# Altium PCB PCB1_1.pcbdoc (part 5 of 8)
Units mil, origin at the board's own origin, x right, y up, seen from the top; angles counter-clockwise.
Board outline 3937.01 x 3346.46 mil, 6 copper layers (Top Layer, Signal-1, SIG, POWER, Signal-4, Bottom Layer), stack 60.565 mil thick; 256 components, 201 nets, 1360 pads, 815 vias.
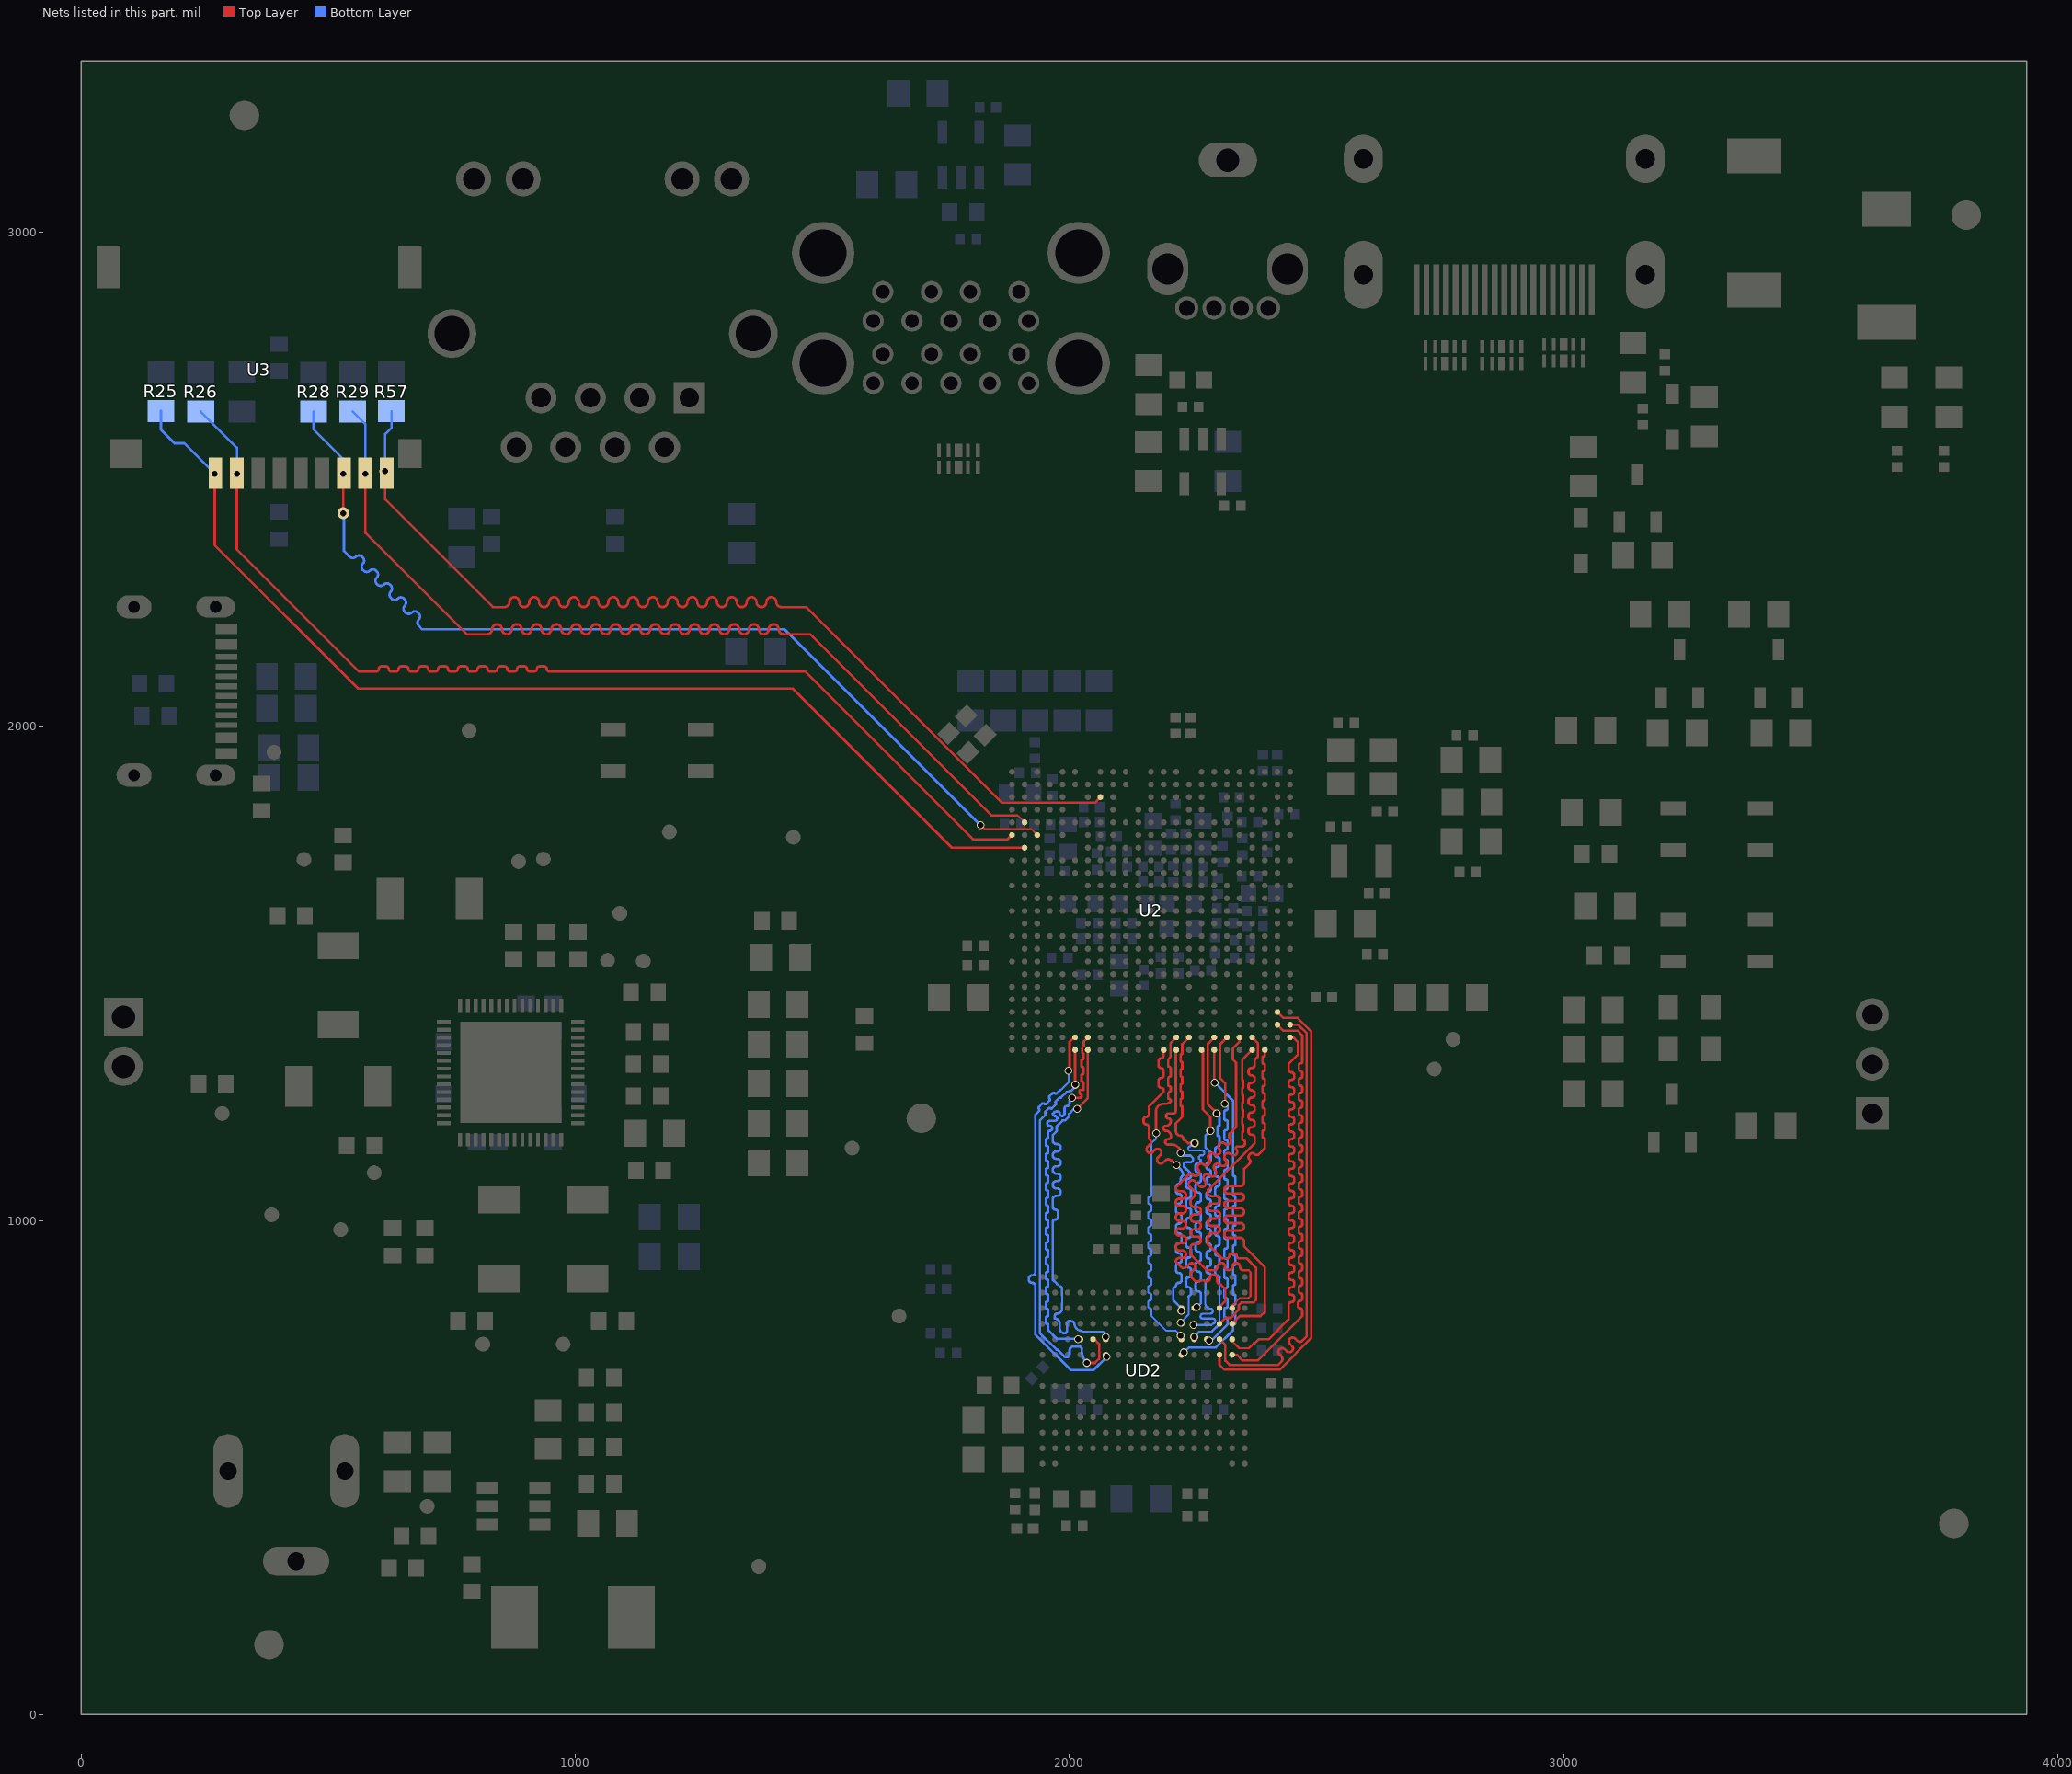
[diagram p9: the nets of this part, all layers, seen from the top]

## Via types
v1: diameter 16, hole 12, Top Layer to Bottom Layer, 426 vias
v2: diameter 24, hole 12, Top Layer to Bottom Layer, 385 vias
v3: diameter 34, hole 12, Top Layer to Bottom Layer, 2 vias
v4: diameter 30, hole 12, Top Layer to Bottom Layer, 2 vias

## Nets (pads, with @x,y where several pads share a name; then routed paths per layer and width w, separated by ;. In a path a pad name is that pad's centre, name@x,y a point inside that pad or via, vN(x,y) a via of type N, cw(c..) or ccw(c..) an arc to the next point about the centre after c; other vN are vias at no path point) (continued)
SDC0-D0: R28.1 U2.F3 U3.7 | length 2051.8
  Top Layer w4: v1(1820,1800.06) 1820.17,1800.06 1827.86,1792.36 1921.32,1792.36 1921.41,1792.28 1922.58,1792.28 1934.69,1780.17 U2.F3@1934.69,1780
  Top Layer w5: v2(530,2431.46) v2(530,2511.46) U3.7@531.26,2512.8
  Bottom Layer w5: R28.1@470.16,2637.13 470.16,2601.29 530,2541.46 v2(530,2511.46) ; v2(530,2431.46) 531.46,2429.99 531.46,2354.99 543.09,2343.37 ccw(c549.34,2349.62) 555.59,2343.37 cw(c561.84,2337.12) 568.09,2343.37 569.73,2341.73 cw(c563.48,2335.48) 569.73,2329.23 ccw(c575.98,2322.98) 569.73,2316.73 571.37,2315.08 ccw(c577.62,2321.33) 583.87,2315.08 cw(c590.12,2308.83) 596.37,2315.08 598.01,2313.44 cw(c591.76,2307.19) 598.01,2300.94 ccw(c604.26,2294.69) 598.01,2288.44 599.66,2286.8 ccw(c605.91,2293.05) 612.16,2286.8 cw(c618.41,2280.55) 624.66,2286.8 626.3,2285.16 cw(c620.05,2278.91) 626.3,2272.66 ccw(c632.55,2266.41) 626.3,2260.16 627.94,2258.52 ccw(c634.19,2264.77) 640.44,2258.52 cw(c646.69,2252.27) 652.94,2258.52 654.58,2256.87 cw(c648.33,2250.62) 654.58,2244.37 ccw(c660.83,2238.12) 654.58,2231.87 656.23,2230.23 ccw(c662.48,2236.48) 668.73,2230.23 cw(c674.98,2223.98) 681.23,2230.23 682.87,2228.59 cw(c676.62,2222.34) 682.87,2216.09 ccw(c689.12,2209.84) 682.87,2203.59 690,2196.46 1423.6,2196.46 v1(1820,1800.06)
SDC0-D1: R29.1 U2.E2 U3.8 | length 2175.2
  Top Layer w4: 1841.96,1819.5 1895.19,1819.5 U2.E2@1909.09,1805.59
  Top Layer w5: v2(575,2511.46) 575,2391.46 780,2186.46 821.28,2186.46 ccw(c821.28,2196.46) 831.28,2196.46 cw(c841.28,2196.46) 851.28,2196.46 ccw(c861.28,2196.46) 871.28,2196.46 cw(c881.28,2196.46) 891.28,2196.46 ccw(c901.28,2196.46) 911.28,2196.46 cw(c921.28,2196.46) 931.28,2196.46 ccw(c941.28,2196.46) 951.28,2196.46 cw(c961.28,2196.46) 971.28,2196.46 ccw(c981.28,2196.46) 991.28,2196.46 cw(c1001.28,2196.46) 1011.28,2196.46 ccw(c1021.28,2196.46) 1031.28,2196.46 cw(c1041.28,2196.46) 1051.28,2196.46 ccw(c1061.28,2196.46) 1071.28,2196.46 cw(c1081.28,2196.46) 1091.28,2196.46 ccw(c1101.28,2196.46) 1111.28,2196.46 cw(c1121.28,2196.46) 1131.28,2196.46 ccw(c1141.28,2196.46) 1151.28,2196.46 cw(c1161.28,2196.46) 1171.28,2196.46 ccw(c1181.28,2196.46) 1191.28,2196.46 cw(c1201.28,2196.46) 1211.28,2196.46 ccw(c1221.28,2196.46) 1231.28,2196.46 cw(c1241.28,2196.46) 1251.28,2196.46 ccw(c1261.28,2196.46) 1271.28,2196.46 cw(c1281.28,2196.46) 1291.28,2196.46 ccw(c1301.28,2196.46) 1311.28,2196.46 cw(c1321.28,2196.46) 1331.28,2196.46 ccw(c1341.28,2196.46) 1351.28,2196.46 cw(c1361.28,2196.46) 1371.28,2196.46 ccw(c1381.28,2196.46) 1391.28,2196.46 cw(c1401.28,2196.46) 1411.28,2196.46 ccw(c1421.28,2196.46) 1421.28,2186.46 1475,2186.46 1841.68,1819.78
  Bottom Layer w5: R29.1@549.18,2637.16 575,2611.33 v2(575,2511.46)
SDC0-D2: R25.1 U2.G2 U3.1 | length 2221.5
  Top Layer w5: v2(270,2511.46) 270,2366.46 560,2076.46 1440,2076.46 1762.05,1754.41 U2.G2@1909.09,1754.41
  Bottom Layer w5: R25.1@161.03,2638.49 161.03,2600.43 188.54,2572.92 208.54,2572.92 v2(270,2511.46)
SDC0-D3: R26.1 U2.F1 U3.2 | length 2228.8
  Top Layer w5: U3.2@314.72,2512.8 314.72,2358.32 561.58,2111.46 597.02,2111.46 ccw(c597.02,2116.46) 602.02,2116.46 cw(c607.02,2116.46) 607.02,2121.46 617.02,2121.46 cw(c617.02,2116.46) 622.02,2116.46 ccw(c627.02,2116.46) 627.02,2111.46 637.02,2111.46 ccw(c637.02,2116.46) 642.02,2116.46 cw(c647.02,2116.46) 647.02,2121.46 657.02,2121.46 cw(c657.02,2116.46) 662.02,2116.46 ccw(c667.02,2116.46) 667.02,2111.46 677.02,2111.46 ccw(c677.02,2116.46) 682.02,2116.46 cw(c687.02,2116.46) 687.02,2121.46 697.02,2121.46 cw(c697.02,2116.46) 702.02,2116.46 ccw(c707.02,2116.46) 707.02,2111.46 717.02,2111.46 ccw(c717.02,2116.46) 722.02,2116.46 cw(c727.02,2116.46) 727.02,2121.46 737.02,2121.46 cw(c737.02,2116.46) 742.02,2116.46 ccw(c747.02,2116.46) 747.02,2111.46 757.02,2111.46 ccw(c757.02,2116.46) 762.02,2116.46 cw(c767.02,2116.46) 767.02,2121.46 777.02,2121.46 cw(c777.02,2116.46) 782.02,2116.46 ccw(c787.02,2116.46) 787.02,2111.46 797.02,2111.46 ccw(c797.02,2116.46) 802.02,2116.46 cw(c807.02,2116.46) 807.02,2121.46 817.02,2121.46 cw(c817.02,2116.46) 822.02,2116.46 ccw(c827.02,2116.46) 827.02,2111.46 837.02,2111.46 ccw(c837.02,2116.46) 842.02,2116.46 cw(c847.02,2116.46) 847.02,2121.46 857.02,2121.46 cw(c857.02,2116.46) 862.02,2116.46 ccw(c867.02,2116.46) 867.02,2111.46 877.02,2111.46 ccw(c877.02,2116.46) 882.02,2116.46 cw(c887.02,2116.46) 887.02,2121.46 897.02,2121.46 cw(c897.02,2116.46) 902.02,2116.46 ccw(c907.02,2116.46) 907.02,2111.46 917.02,2111.46 ccw(c917.02,2116.46) 922.02,2116.46 cw(c927.02,2116.46) 927.02,2121.46 937.02,2121.46 cw(c937.02,2116.46) 942.02,2116.46 ccw(c947.02,2116.46) 947.02,2111.46 1464.81,2111.46 1804.81,1771.46 1874.96,1771.46 U2.F1@1883.5,1780
  Bottom Layer w5: R26.1@241.48,2637.19 315,2563.67 v2(315,2511.46)
SDC0-DET: R57.1 U2.C8 U3.CD | length 2210.1
  Top Layer w5: v2(615,2516.46) 615,2459.18 832.73,2241.46 856.53,2241.46 ccw(c856.53,2251.46) 866.53,2251.46 cw(c876.53,2251.46) 886.53,2251.46 ccw(c896.53,2251.46) 906.53,2251.46 cw(c916.53,2251.46) 926.53,2251.46 ccw(c936.53,2251.46) 946.53,2251.46 cw(c956.53,2251.46) 966.53,2251.46 ccw(c976.53,2251.46) 986.53,2251.46 cw(c996.53,2251.46) 1006.53,2251.46 ccw(c1016.53,2251.46) 1026.53,2251.46 cw(c1036.53,2251.46) 1046.53,2251.46 ccw(c1056.53,2251.46) 1066.53,2251.46 cw(c1076.53,2251.46) 1086.53,2251.46 ccw(c1096.53,2251.46) 1106.53,2251.46 cw(c1116.53,2251.46) 1126.53,2251.46 ccw(c1136.53,2251.46) 1146.53,2251.46 cw(c1156.53,2251.46) 1166.53,2251.46 ccw(c1176.53,2251.46) 1186.53,2251.46 cw(c1196.53,2251.46) 1206.53,2251.46 ccw(c1216.53,2251.46) 1226.53,2251.46 cw(c1236.53,2251.46) 1246.53,2251.46 ccw(c1256.53,2251.46) 1266.53,2251.46 cw(c1276.53,2251.46) 1286.53,2251.46 ccw(c1296.53,2251.46) 1306.53,2251.46 cw(c1316.53,2251.46) 1326.53,2251.46 ccw(c1336.53,2251.46) 1346.53,2251.46 cw(c1356.53,2251.46) 1366.53,2251.46 ccw(c1376.53,2251.46) 1386.53,2251.46 cw(c1396.53,2251.46) 1406.53,2251.46 ccw(c1416.53,2251.46) 1416.53,2241.46 1467.17,2241.46 1863.26,1845.37 2051.23,1845.37 U2.C8@2062.64,1856.77
  Bottom Layer w5: v2(615,2516.46) 615,2591.46 627.65,2604.11 R57.1@627.65,2637.78
SDQ0: U2.AB18 UD2.P9 | length 731
  Top Layer w5: v1(2314.55,1236.01) 2315,1236.46 2315,1277.67 2305,1287.67 2305,1357.01 U2.AB18@2318.54,1370.55
  Bottom Layer w5: v1(2282.95,756.95) 2287.49,756.98 2320,789.49 2320,799.4 ccw(c2316.53,799.4) 2316.53,802.88 cw(c2316.53,806.35) 2313.05,806.35 2313.05,819.4 cw(c2316.53,819.4) 2316.53,822.88 ccw(c2316.53,826.35) 2320,826.35 2320,839.4 ccw(c2316.53,839.4) 2316.53,842.88 cw(c2316.53,846.35) 2313.05,846.35 2313.05,859.4 cw(c2316.53,859.4) 2316.53,862.88 ccw(c2316.53,866.35) 2320,866.35 2320,879.4 ccw(c2316.53,879.4) 2316.53,882.88 cw(c2316.53,886.35) 2313.05,886.35 2313.05,899.4 cw(c2316.53,899.4) 2316.53,902.88 ccw(c2316.53,906.35) 2320,906.35 2320,919.4 ccw(c2316.53,919.4) 2316.53,922.88 cw(c2316.53,926.35) 2313.05,926.35 2313.05,939.4 cw(c2316.53,939.4) 2316.53,942.88 ccw(c2316.53,946.35) 2320,946.35 2320,959.4 ccw(c2316.53,959.4) 2316.53,962.88 cw(c2316.53,966.35) 2313.05,966.35 2313.05,979.4 cw(c2316.53,979.4) 2316.53,982.88 ccw(c2316.53,986.35) 2320,986.35 2320,999.4 ccw(c2316.53,999.4) 2316.53,1002.88 cw(c2316.53,1006.35) 2313.05,1006.35 2313.05,1019.4 cw(c2316.53,1019.4) 2316.53,1022.88 ccw(c2316.53,1026.35) 2320,1026.35 2320,1039.4 ccw(c2316.53,1039.4) 2316.53,1042.88 cw(c2316.53,1046.35) 2313.05,1046.35 2313.05,1059.4 cw(c2316.53,1059.4) 2316.53,1062.88 ccw(c2316.53,1066.35) 2320,1066.35 2320,1079.4 ccw(c2316.53,1079.4) 2316.53,1082.88 cw(c2316.53,1086.35) 2313.05,1086.35 2313.05,1099.4 cw(c2316.53,1099.4) 2316.53,1102.88 ccw(c2316.53,1106.35) 2320,1106.35 2320,1119.4 ccw(c2316.53,1119.4) 2316.53,1122.88 cw(c2316.53,1126.35) 2313.05,1126.35 2313.05,1139.4 cw(c2316.53,1139.4) 2316.53,1142.88 ccw(c2316.53,1146.35) 2320,1146.35 2320,1159.4 ccw(c2316.53,1159.4) 2316.53,1162.88 cw(c2316.53,1166.35) 2313.05,1166.35 2313.05,1179.4 cw(c2316.53,1179.4) 2316.53,1182.88 ccw(c2316.53,1186.35) 2320,1186.35 2320,1199.4 ccw(c2316.53,1199.4) 2316.53,1202.88 cw(c2316.53,1206.35) 2313.05,1206.35 2313.05,1219.4 cw(c2316.53,1219.4) 2316.53,1222.88 ccw(c2316.53,1226.35) 2320,1226.35 2320,1230.56 v1(2314.55,1236.01)
SDQ1: U2.AC17 UD2.M8 | length 742
  Top Layer w5: U2.AC17@2292.95,1344.96 2292.95,1279.94 v1(2294,1278.9)
  Bottom Layer w5: v1(2231.77,732.95) 2241.77,742.95 2296.5,742.95 2331,777.46 2331,787.33 cw(c2333.25,787.33) 2333.25,789.58 ccw(c2333.25,791.83) 2335.5,791.83 2335.5,807.33 ccw(c2333.25,807.33) 2333.25,809.58 cw(c2333.25,811.83) 2331,811.83 2331,827.33 cw(c2333.25,827.33) 2333.25,829.58 ccw(c2333.25,831.83) 2335.5,831.83 2335.5,847.33 ccw(c2333.25,847.33) 2333.25,849.58 cw(c2333.25,851.83) 2331,851.83 2331,867.33 cw(c2333.25,867.33) 2333.25,869.58 ccw(c2333.25,871.83) 2335.5,871.83 2335.5,887.33 ccw(c2333.25,887.33) 2333.25,889.58 cw(c2333.25,891.83) 2331,891.83 2331,907.33 cw(c2333.25,907.33) 2333.25,909.58 ccw(c2333.25,911.83) 2335.5,911.83 2335.5,927.33 ccw(c2333.25,927.33) 2333.25,929.58 cw(c2333.25,931.83) 2331,931.83 2331,947.33 cw(c2333.25,947.33) 2333.25,949.58 ccw(c2333.25,951.83) 2335.5,951.83 2335.5,967.33 ccw(c2333.25,967.33) 2333.25,969.58 cw(c2333.25,971.83) 2331,971.83 2331,987.33 cw(c2333.25,987.33) 2333.25,989.58 ccw(c2333.25,991.83) 2335.5,991.83 2335.5,1007.33 ccw(c2333.25,1007.33) 2333.25,1009.58 cw(c2333.25,1011.83) 2331,1011.83 2331,1027.33 cw(c2333.25,1027.33) 2333.25,1029.58 ccw(c2333.25,1031.83) 2335.5,1031.83 2335.5,1047.33 ccw(c2333.25,1047.33) 2333.25,1049.58 cw(c2333.25,1051.83) 2331,1051.83 2331,1067.33 cw(c2333.25,1067.33) 2333.25,1069.58 ccw(c2333.25,1071.83) 2335.5,1071.83 2335.5,1087.33 ccw(c2333.25,1087.33) 2333.25,1089.58 cw(c2333.25,1091.83) 2331,1091.83 2331,1241.9 v1(2294,1278.9)
SDQ2: U2.AB17 UD2.N9 | length 730.7
  Top Layer w5: U2.AB17@2292.95,1370.55 2280,1357.6 2280,1235.01 v1@2298.55,1216.46
  Bottom Layer w3.5: 2304.05,790.51 2304.05,883.83
  Bottom Layer w5: v1(2252.36,764.45) 2262.36,774.45 2287.99,774.45 2304.05,790.51 ; v1@2298.55,1216.46 2303.55,1211.46 2303.55,1192.88 cw(c2301.55,1192.88) 2301.55,1190.88 ccw(c2301.55,1188.88) 2299.55,1188.88 2299.55,1172.88 ccw(c2301.55,1172.88) 2301.55,1170.88 cw(c2301.55,1168.88) 2303.55,1168.88 2303.55,1152.88 cw(c2299.28,1152.88) 2299.28,1148.61 ccw(c2299.28,1144.33) 2295,1144.33 2295,1132.88 ccw(c2299.28,1132.88) 2299.28,1128.61 cw(c2299.28,1124.33) 2303.55,1124.33 2303.55,1112.88 cw(c2299.28,1112.88) 2299.28,1108.61 ccw(c2299.28,1104.33) 2295,1104.33 2295,1092.88 ccw(c2299.28,1092.88) 2299.28,1088.61 cw(c2299.28,1084.33) 2303.55,1084.33 2303.55,1072.88 cw(c2299.28,1072.88) 2299.28,1068.61 ccw(c2299.28,1064.33) 2295,1064.33 2295,1052.88 ccw(c2299.28,1052.88) 2299.28,1048.61 cw(c2299.28,1044.33) 2303.55,1044.33 2303.55,1032.88 cw(c2299.28,1032.88) 2299.28,1028.61 ccw(c2299.28,1024.33) 2295,1024.33 2295,1012.88 ccw(c2299.28,1012.88) 2299.28,1008.61 cw(c2299.28,1004.33) 2303.55,1004.33 2303.55,992.88 cw(c2299.28,992.88) 2299.28,988.61 ccw(c2299.28,984.33) 2295,984.33 2295,972.88 ccw(c2299.28,972.88) 2299.28,968.61 cw(c2299.28,964.33) 2303.55,964.33 2303.55,952.88 cw(c2299.28,952.88) 2299.28,948.61 ccw(c2299.28,944.33) 2295,944.33 2295,932.88 ccw(c2299.28,932.88) 2299.28,928.61 cw(c2299.28,924.33) 2303.55,924.33 2303.55,912.88 cw(c2299.28,912.88) 2299.28,908.61 ccw(c2299.28,904.33) 2295,904.33 2295,892.88 ccw(c2299.28,892.88) 2299.28,888.61 cw(c2299.28,884.33) 2303.55,884.33 2304.05,883.83
  other v1: 2298,1216.46
SDQ3: U2.AC16 UD2.N10 | length 752.7
  Top Layer w5: U2.AC16@2267.36,1344.96 2270,1342.32 2270,1224.66 2285,1209.66 v1(2285,1181.51)
  Bottom Layer w4: v1(2250.72,788.25) 2287.31,788.25 2290,790.94 ccw(c2290,795.94) 2295,795.94 ccw(c2289.49,795.94) 2289.49,801.46 2269,801.46 cw(c2269,805.46) 2265,805.46 cw(c2271,805.46) 2271,811.46 2285,811.46 ccw(c2285,816.46) 2290,816.46 ccw(c2285,816.46) 2285,821.46 cw(c2285,831.46) 2275,831.46 2274.63,831.82 2274.63,861.09 2275,861.46
  Bottom Layer w5: 2275,861.46 2275,876.5 2286,887.5 2286,888.68 ccw(c2281.63,888.68) 2281.63,893.05 cw(c2281.63,897.42) 2277.26,897.42 2277.26,903.68 cw(c2281.63,903.68) 2281.63,908.05 ccw(c2281.63,912.42) 2286,912.42 2286,918.68 ccw(c2281.63,918.68) 2281.63,923.05 cw(c2281.63,927.42) 2277.26,927.42 2277.26,933.68 cw(c2281.63,933.68) 2281.63,938.05 ccw(c2281.63,942.42) 2286,942.42 2286,948.68 ccw(c2281.63,948.68) 2281.63,953.05 cw(c2281.63,957.42) 2277.26,957.42 2277.26,963.68 cw(c2281.63,963.68) 2281.63,968.05 ccw(c2281.63,972.42) 2286,972.42 2286,978.68 ccw(c2281.63,978.68) 2281.63,983.05 cw(c2281.63,987.42) 2277.26,987.42 2277.26,993.68 cw(c2281.63,993.68) 2281.63,998.05 ccw(c2281.63,1002.42) 2286,1002.42 2286,1008.68 ccw(c2281.63,1008.68) 2281.63,1013.05 cw(c2281.63,1017.42) 2277.26,1017.42 2277.26,1023.68 cw(c2281.63,1023.68) 2281.63,1028.05 ccw(c2281.63,1032.42) 2286,1032.42 2286,1038.68 ccw(c2281.63,1038.68) 2281.63,1043.05 cw(c2281.63,1047.42) 2277.26,1047.42 2277.26,1053.68 cw(c2281.63,1053.68) 2281.63,1058.05 ccw(c2281.63,1062.42) 2286,1062.42 2286,1068.68 ccw(c2281.63,1068.68) 2281.63,1073.05 cw(c2281.63,1077.42) 2277.26,1077.42 2277.26,1083.68 cw(c2281.63,1083.68) 2281.63,1088.05 ccw(c2281.63,1092.42) 2286,1092.42 2286,1098.68 ccw(c2281.63,1098.68) 2281.63,1103.05 cw(c2281.63,1107.42) 2277.26,1107.42 2277.26,1113.68 cw(c2281.63,1113.68) 2281.63,1118.05 ccw(c2281.63,1122.42) 2286,1122.42 2286,1137.48 2275,1148.48 2275,1171.51 v1(2285,1181.51)
SDQ4: U2.AB15 UD2.N11 | length 737.8
  Top Layer w5: U2.AB15@2241.77,1370.55 2228.18,1356.96 2228.18,1337.65 cw(c2226.59,1337.65) 2226.59,1336.05 ccw(c2226.59,1334.46) 2225,1334.46 2225,1322.65 ccw(c2226.59,1322.65) 2226.59,1321.05 cw(c2226.59,1319.46) 2228.18,1319.46 2228.18,1307.65 cw(c2226.59,1307.65) 2226.59,1306.05 ccw(c2226.59,1304.46) 2225,1304.46 2225,1292.65 ccw(c2226.59,1292.65) 2226.59,1291.05 cw(c2226.59,1289.46) 2228.18,1289.46 2228.18,1277.65 cw(c2226.59,1277.65) 2226.59,1276.05 ccw(c2226.59,1274.46) 2225,1274.46 2225,1262.65 ccw(c2226.59,1262.65) 2226.59,1261.05 cw(c2226.59,1259.46) 2228.18,1259.46 2228.18,1247.65 cw(c2226.59,1247.65) 2226.59,1246.05 ccw(c2226.59,1244.46) 2225,1244.46 2225,1232.65 ccw(c2226.59,1232.65) 2226.59,1231.05 cw(c2226.59,1229.46) 2228.18,1229.46 2228.18,1209.64 2215,1196.46 2215,1181.46 ccw(c2225,1181.46) 2225,1171.46 cw(c2225,1166.46) 2230,1166.46 ccw(c2235,1166.46) 2235,1161.46 2240,1156.46 v1(2253.33,1156.46)
  Bottom Layer w4: 2244.13,1149.96 2242.54,1149.96 2240.05,1147.47 2240.05,1143.95 2242.54,1141.46 2270,1141.46 2272.83,1138.63 2272.83,1134.78 2269.85,1131.8 2265,1131.8 2262.17,1128.97 2262.17,1124.97 2265.23,1121.92 2266.13,1121.92
  Bottom Layer w5: 2244.13,1149.96 2245.63,1151.46 2251.25,1151.46 2253.33,1153.53 v1(2253.33,1156.46) ; v1(2257.8,824.29) 2266.13,832.62 2266.13,851.05 ccw(c2260.7,851.05) 2260.7,856.49 cw(c2260.7,861.92) 2255.27,861.92 2255.27,871.05 cw(c2260.7,871.05) 2260.7,876.49 ccw(c2260.7,881.92) 2266.13,881.92 2266.13,891.05 ccw(c2260.7,891.05) 2260.7,896.49 cw(c2260.7,901.92) 2255.27,901.92 2255.27,911.05 cw(c2260.7,911.05) 2260.7,916.49 ccw(c2260.7,921.92) 2266.13,921.92 2266.13,931.05 ccw(c2260.7,931.05) 2260.7,936.49 cw(c2260.7,941.92) 2255.27,941.92 2255.27,951.05 cw(c2260.7,951.05) 2260.7,956.49 ccw(c2260.7,961.92) 2266.13,961.92 2266.13,971.05 ccw(c2260.7,971.05) 2260.7,976.49 cw(c2260.7,981.92) 2255.27,981.92 2255.27,991.05 cw(c2260.7,991.05) 2260.7,996.49 ccw(c2260.7,1001.92) 2266.13,1001.92 2266.13,1011.05 ccw(c2260.7,1011.05) 2260.7,1016.49 cw(c2260.7,1021.92) 2255.27,1021.92 2255.27,1031.05 cw(c2260.7,1031.05) 2260.7,1036.49 ccw(c2260.7,1041.92) 2266.13,1041.92 2266.13,1051.05 ccw(c2260.7,1051.05) 2260.7,1056.49 cw(c2260.7,1061.92) 2255.27,1061.92 2255.27,1071.05 cw(c2260.7,1071.05) 2260.7,1076.49 ccw(c2260.7,1081.92) 2266.13,1081.92 2266.13,1091.05 ccw(c2260.7,1091.05) 2260.7,1096.49 cw(c2260.7,1101.92) 2255.27,1101.92 2255.27,1111.05 cw(c2260.7,1111.05) 2260.7,1116.49 ccw(c2260.7,1121.92) 2266.13,1121.92
SDQ5: U2.AB14 UD2.M9 | length 742.5
  Top Layer w5: v1(2175.32,1176.77) cw(c2176.08,1177.53) 2175,1177.53 2175,1220.25 cw(c2191.21,1220.25) 2179.75,1231.71 cw(c2190,1221.46) 2190,1235.96 2193.43,1235.96 ccw(c2193.43,1252.67) 2205.25,1240.85 ccw(c2204.65,1241.46) 2205.5,1241.46 ccw(c2200.5,1241.46) 2200.5,1246.46 cw(c2200.5,1246.96) 2200,1246.96 2200,1256.46 cw(c2205,1256.46) 2205,1261.46 2205,1268.96 ccw(c2202.5,1268.96) 2202.5,1271.46 cw(c2202.5,1273.96) 2200,1273.96 2200,1286.46 cw(c2205,1286.46) 2205,1291.46 2205,1306.46 ccw(c2200,1306.46) 2200,1311.46 2200,1326.46 2204.28,1330.73 2204.28,1358.65 U2.AB14@2216.18,1370.55
  Bottom Layer w4: v1(2175.32,1176.77) 2175.32,1165.86 2165.5,1156.05 2165.5,1050.84 cw(c2162.38,1050.84) 2162.38,1047.72 ccw(c2162.38,1044.6) 2159.26,1044.6 2159.26,1035.84 ccw(c2162.38,1035.84) 2162.38,1032.72 cw(c2162.38,1029.6) 2165.5,1029.6 2165.5,1020.84 cw(c2162.38,1020.84) 2162.38,1017.72 ccw(c2162.38,1014.6) 2159.26,1014.6 2159.26,1005.84 ccw(c2162.38,1005.84) 2162.38,1002.72 cw(c2162.38,999.6) 2165.5,999.6 2165.5,990.84 cw(c2162.38,990.84) 2162.38,987.72 ccw(c2162.38,984.6) 2159.26,984.6 2159.26,975.84 ccw(c2162.38,975.84) 2162.38,972.72 cw(c2162.38,969.6) 2165.5,969.6 2165.5,960.84 cw(c2162.38,960.84) 2162.38,957.72 ccw(c2162.38,954.6) 2159.26,954.6 2159.26,945.84 ccw(c2162.38,945.84) 2162.38,942.72 cw(c2162.38,939.6) 2165.5,939.6 2165.5,930.84 cw(c2162.38,930.84) 2162.38,927.72 ccw(c2162.38,924.6) 2159.26,924.6 2159.26,915.84 ccw(c2162.38,915.84) 2162.38,912.72 cw(c2162.38,909.6) 2165.5,909.6 2165.5,900.84 cw(c2162.38,900.84) 2162.38,897.72 ccw(c2162.38,894.6) 2159.26,894.6 2159.26,885.84 ccw(c2162.38,885.84) 2162.38,882.72 cw(c2162.38,879.6) 2165.5,879.6 2165.5,870.84 cw(c2162.38,870.84) 2162.38,867.72 ccw(c2162.38,864.6) 2159.26,864.6 2159.26,855.84 ccw(c2162.38,855.84) 2162.38,852.72 cw(c2162.38,849.6) 2165.5,849.6 2165.5,840.84 cw(c2162.38,840.84) 2162.38,837.72 ccw(c2162.38,834.6) 2159.26,834.6 2159.26,825.84 ccw(c2162.38,825.84) 2162.38,822.72 cw(c2162.38,819.6) 2165.5,819.6 2165.5,806.83 2195.38,776.94 2214.51,776.94 v1(2225,766.46)
SDQ6: U2.AC14 UD2.M10 | length 736.8
  Top Layer w5: U2.AC14@2216.18,1344.96 ccw(c2216.18,1343.78) 2215,1343.78 2215,1221.46 cw(c2210,1221.46) 2210,1216.46 2200,1216.46 ccw(c2200,1211.46) 2195,1211.46 ccw(c2200,1211.46) 2200,1206.46 cw(c2200,1201.46) 2205,1201.46 cw(c2195,1201.46) 2195,1191.46 ccw(c2195,1186.46) 2190,1186.46 ccw(c2195,1186.46) 2195,1181.46 cw(c2195,1170.92) 2205.54,1170.92 2205.54,1170.4 cw(c2199.71,1170.4) 2199.71,1164.58 ccw(c2199.71,1158.58) 2193.71,1158.58 ccw(c2198.71,1158.58) 2198.71,1153.58 2206.64,1153.58 cw(c2206.64,1133.51) v1@2226.71,1133.51
  Bottom Layer w4: v1(2224.87,793.21) 2241.27,809.61 2241.27,844.78 2240.77,845.28
  Bottom Layer w5: v1(2225,1136.46) 2230,1131.46 2245,1131.46 2250,1126.46 2250,1121.46 2246.46,1117.92 2235,1117.92 2231.46,1114.39 2231.46,1109.39 2245.77,1095.08 2245.77,1089.56 cw(c2241.02,1089.56) 2241.02,1084.81 ccw(c2241.02,1080.06) 2236.27,1080.06 2236.27,1069.56 ccw(c2241.02,1069.56) 2241.02,1064.81 cw(c2241.02,1060.06) 2245.77,1060.06 2245.77,1049.56 cw(c2241.02,1049.56) 2241.02,1044.81 ccw(c2241.02,1040.06) 2236.27,1040.06 2236.27,1029.56 ccw(c2241.02,1029.56) 2241.02,1024.81 cw(c2241.02,1020.06) 2245.77,1020.06 2245.77,1009.56 cw(c2241.02,1009.56) 2241.02,1004.81 ccw(c2241.02,1000.06) 2236.27,1000.06 2236.27,989.56 ccw(c2241.02,989.56) 2241.02,984.81 cw(c2241.02,980.06) 2245.77,980.06 2245.77,969.56 cw(c2241.02,969.56) 2241.02,964.81 ccw(c2241.02,960.06) 2236.27,960.06 2236.27,949.56 ccw(c2241.02,949.56) 2241.02,944.81 cw(c2241.02,940.06) 2245.77,940.06 2245.77,929.56 cw(c2241.02,929.56) 2241.02,924.81 ccw(c2241.02,920.06) 2236.27,920.06 2236.27,909.56 ccw(c2241.02,909.56) 2241.02,904.81 cw(c2241.02,900.06) 2245.77,900.06 2245.77,889.56 cw(c2241.02,889.56) 2241.02,884.81 ccw(c2241.02,880.06) 2236.27,880.06 2236.27,869.56 ccw(c2241.02,869.56) 2241.02,864.81 cw(c2241.02,860.06) 2245.77,860.06 2245.77,850.28 2240.77,845.28
SDQ7: U2.AC13 UD2.M11 | length 742.1
  Top Layer w5: U2.AC13@2190.59,1344.96 2190.59,1333.68 cw(c2185.3,1333.68) 2185.3,1328.38 ccw(c2185.3,1323.09) 2180,1323.09 2180,1313.68 ccw(c2185.3,1313.68) 2185.3,1308.38 cw(c2185.3,1303.09) 2190.59,1303.09 2190.59,1293.68 cw(c2185.3,1293.68) 2185.3,1288.38 ccw(c2185.3,1283.09) 2180,1283.09 2180,1273.68 ccw(c2185.3,1273.68) 2185.3,1268.38 cw(c2185.3,1263.09) 2190.59,1263.09 2190.59,1260.48 2160.5,1230.39 2160.5,1214.72 cw(c2155.25,1214.72) 2155.25,1209.47 ccw(c2155.25,1204.22) 2150,1204.22 2150,1199.72 ccw(c2155.25,1199.72) 2155.25,1194.47 cw(c2155.25,1189.22) 2160.5,1189.22 2160.5,1166.08 2162.52,1164.06 cw(c2157.21,1158.76) 2162.52,1153.46 2158.3,1149.24 ccw(c2163.6,1143.93) 2168.9,1138.63 2173.12,1142.85 cw(c2178.43,1137.55) 2183.73,1132.24 2179.51,1128.02 ccw(c2184.81,1122.72) 2190.12,1117.42 2194.34,1121.64 cw(c2199.64,1116.33) 2204.94,1121.64 2206.94,1121.64 v1(2216.17,1112.41)
  Bottom Layer w5: v1(2216.17,1112.41) 2223.64,1104.94 ccw(c2231.46,1109.39) 2225.1,1103.02 2225.29,1102.84 cw(c2213.91,1091.46) 2230,1091.46 2228.2,1089.66 ccw(c2235.93,1081.93) 2225,1081.93 cw(c2214.07,1081.93) 2221.8,1074.2 2221.23,1073.63 ccw(c2221.23,1068.08) 2215.68,1068.08 2215.68,1059.17 ccw(c2221.23,1059.17) 2221.23,1053.63 cw(c2221.23,1048.08) 2226.77,1048.08 2226.77,1039.17 cw(c2221.23,1039.17) 2221.23,1033.63 ccw(c2221.23,1028.08) 2215.68,1028.08 2215.68,1019.17 ccw(c2221.23,1019.17) 2221.23,1013.63 cw(c2221.23,1008.08) 2226.77,1008.08 2226.77,999.17 cw(c2221.23,999.17) 2221.23,993.63 ccw(c2221.23,988.08) 2215.68,988.08 2215.68,979.17 ccw(c2221.23,979.17) 2221.23,973.63 cw(c2221.23,968.08) 2226.77,968.08 2226.77,959.17 cw(c2221.23,959.17) 2221.23,953.63 ccw(c2221.23,948.08) 2215.68,948.08 2215.68,939.17 ccw(c2221.23,939.17) 2221.23,933.63 cw(c2221.23,928.08) 2226.77,928.08 2226.77,919.17 cw(c2221.23,919.17) 2221.23,913.63 ccw(c2221.23,908.08) 2215.68,908.08 2215.68,899.17 ccw(c2221.23,899.17) 2221.23,893.63 cw(c2221.23,888.08) 2226.77,888.08 2226.77,879.17 cw(c2221.23,879.17) 2221.23,873.63 ccw(c2221.23,868.08) 2215.68,868.08 2210.18,862.58 2210.18,838.53 2226.34,822.37 v1(2226.34,816.94)
SDQ8: U2.AB19 UD2.R11 | length 941.8
  Top Layer w5: UD2.R11@2303.54,822.44 2303.54,824.89 2315,836.35 2315,861.46 2306.46,869.99 cw(c2306.46,877.49) 2298.96,877.49 2298.96,882.69 ccw(c2291.46,882.69) 2283.96,882.69 cw(c2278.48,882.69) 2282.36,878.81 2282.06,878.51 cw(c2277.09,883.48) 2277.09,876.46 cw(c2277.09,881.5) 2273.52,877.93 ccw(c2269.77,868.87) 2266.01,877.93 cw(c2259.77,893.01) 2253.52,877.93 2246.82,884.64 cw(c2252.12,889.94) 2246.82,895.24 2252.35,900.77 ccw(c2247.05,906.08) 2241.74,911.38 2236.21,905.85 cw(c2230.91,911.15) 2225.61,905.85 2215,916.46 cw(c2222.5,916.46) 2222.5,923.96 2228.5,923.96 ccw(c2228.5,931.46) 2228.5,938.96 2222.5,938.96 cw(c2222.5,946.46) 2222.5,953.96 2228.5,953.96 ccw(c2228.5,961.46) 2228.5,968.96 2222.5,968.96 cw(c2222.5,976.46) 2222.5,983.96 2228.5,983.96 ccw(c2228.5,991.46) 2228.5,998.96 2222.5,998.96 cw(c2222.5,1006.46) 2222.5,1013.96 2228.5,1013.96 ccw(c2228.5,1021.46) 2228.5,1028.96 2222.5,1028.96 cw(c2222.5,1036.46) 2222.5,1043.96 2228.5,1043.96 ccw(c2228.5,1051.46) 2228.5,1058.96 2222.5,1058.96 cw(c2222.5,1066.46) 2215,1066.46 2240.41,1091.87 cw(c2245.41,1086.87) 2250.41,1091.87 ccw(c2255.41,1096.87) 2260.41,1091.87 2261.02,1092.47 ccw(c2256.02,1097.47) 2261.02,1102.47 cw(c2266.02,1107.47) 2261.02,1112.47 2261.62,1113.08 cw(c2266.62,1108.08) 2271.62,1113.08 ccw(c2276.62,1118.08) 2281.62,1113.08 2282.23,1113.69 ccw(c2277.23,1118.69) 2282.23,1123.69 cw(c2287.23,1128.69) 2282.23,1133.69 2282.84,1134.29 cw(c2287.84,1129.29) 2292.84,1134.29 ccw(c2297.84,1139.29) 2302.84,1134.29 2303.44,1134.9 ccw(c2298.44,1139.9) 2303.44,1144.9 cw(c2308.44,1149.9) 2303.44,1154.9 2304.05,1155.51 cw(c2309.05,1150.51) 2314.05,1155.51 ccw(c2319.05,1160.51) 2324.05,1155.51 2324.66,1156.11 ccw(c2319.66,1161.11) 2324.66,1166.11 cw(c2329.66,1171.11) 2324.66,1176.11 2337.23,1188.69 2337.23,1319.23 2330.45,1326.01 2330.45,1348.11 2344.13,1361.8 U2.AB19@2344.13,1370.55
SDQ9: U2.AC20 UD2.T11 | length 947.1
  Top Layer w4: UD2.T11@2329.13,822.44 2329.13,827.18 2344.98,843.03 2362.28,843.03 2366.28,847.03 2366.28,895.21 2362.28,899.21
  Top Layer w5: 2245,929.56 2245,931.46 ; 2299.76,906.69 cw(c2292.26,906.69) 2292.26,899.19 2277.26,899.19 2245,931.46 ; 2299.76,906.76 cw(c2307.26,906.76) 2314.76,906.76 ; 2314.76,906.69 ccw(c2322.26,906.69) 2329.76,906.69 ; 2329.76,906.76 cw(c2337.26,906.76) 2344.76,906.76 ; 2344.76,906.69 ccw(c2352.26,906.69) 2352.26,899.19 2362.26,899.19 ; U2.AC20@2369.72,1344.96 2349.38,1324.61 2349.38,1285.07 ccw(c2350.57,1285.07) 2350.57,1283.87 cw(c2350.57,1282.68) 2351.77,1282.68 2351.77,1270.07 cw(c2350.57,1270.07) 2350.57,1268.87 ccw(c2350.57,1267.68) 2349.38,1267.68 2349.38,1255.07 ccw(c2350.57,1255.07) 2350.57,1253.87 cw(c2350.57,1252.68) 2351.77,1252.68 2351.77,1240.07 cw(c2350.57,1240.07) 2350.57,1238.87 ccw(c2350.57,1237.68) 2349.38,1237.68 2349.38,1225.07 ccw(c2350.57,1225.07) 2350.57,1223.87 cw(c2350.57,1222.68) 2351.77,1222.68 2351.77,1210.07 cw(c2350.57,1210.07) 2350.57,1208.87 ccw(c2350.57,1207.68) 2349.38,1207.68 2349.38,1195.07 ccw(c2350.57,1195.07) 2350.57,1193.87 cw(c2350.57,1192.68) 2351.77,1192.68 2351.77,1180.07 cw(c2350.57,1180.07) 2350.57,1178.87 ccw(c2350.57,1177.68) 2349.38,1177.68 2349.38,1163.7 cw(c2349.38,1158.07) 2355,1158.07 2355,1156.46 cw(c2348.23,1156.46) 2348.23,1149.69 2340.82,1149.69 ccw(c2340.82,1145.44) 2336.57,1145.44 ccw(c2338.37,1145.44) 2337.1,1144.16 cw(c2331.79,1138.86) 2326.49,1133.55 2325.96,1134.08 ccw(c2320.66,1128.78) 2315.35,1123.48 2315.88,1122.95 cw(c2310.58,1117.64) 2305.28,1112.34 2304.75,1112.87 ccw(c2299.44,1107.57) 2294.14,1102.26 2294.67,1101.73 cw(c2289.37,1096.43) 2284.06,1091.13 2283.53,1091.66 ccw(c2278.23,1086.35) 2272.93,1081.05 2273.46,1080.52 cw(c2268.15,1075.22) 2262.85,1069.91 2253.66,1079.1 ccw(c2248.36,1073.8) 2243.05,1068.49 2252.24,1059.31 cw(c2246.94,1054) 2252.24,1048.7 2245,1041.46 2245,1034.56 ccw(c2252.5,1034.56) 2252.5,1027.06 2258.63,1027.06 cw(c2258.63,1019.56) 2258.63,1012.06 2252.5,1012.06 ccw(c2252.5,1004.56) 2252.5,997.06 2258.63,997.06 cw(c2258.63,989.56) 2258.63,982.06 2252.5,982.06 ccw(c2252.5,974.56) 2252.5,967.06 2258.63,967.06 cw(c2258.63,959.56) 2258.63,952.06 2252.5,952.06 ccw(c2252.5,944.56) 2245,944.56 2245,931.46
SDQ10: U2.AC21 UD2.T10 | length 958.1
  Top Layer w5: UD2.T10@2329.13,790.94 2344.65,806.46 2386.71,806.46 2395.5,815.24 2395.5,827.67 2395,828.17 2395,905.67 2353.4,947.26 2353.4,957.17 ccw(c2345.9,957.17) 2345.9,964.67 2320.54,964.67 cw(c2320.54,972.17) 2320.54,979.67 2345.9,979.67 ccw(c2345.9,987.17) 2345.9,994.67 2320.54,994.67 cw(c2320.54,1002.17) 2320.54,1009.67 2345.9,1009.67 ccw(c2345.9,1017.17) 2345.9,1024.67 2320.54,1024.67 cw(c2320.54,1032.17) 2320.54,1039.67 2345.9,1039.67 ccw(c2345.9,1047.17) 2345.9,1054.67 2320.54,1054.67 cw(c2320.54,1062.17) 2320.54,1069.67 2345.9,1069.67 ccw(c2345.9,1077.17) 2353.4,1077.17 2353.4,1104.26 2364.01,1114.86 ccw(c2359.54,1119.33) 2364.01,1123.8 cw(c2368.48,1128.27) 2364.01,1132.74 2365.68,1134.41 cw(c2370.15,1129.94) 2374.62,1134.41 ccw(c2379.09,1138.88) 2383.55,1134.41 2395.2,1146.06 2395.2,1164.83 ccw(c2392.91,1164.83) 2392.92,1167.12 cw(c2392.92,1169.4) 2390.63,1169.4 2390.63,1179.83 cw(c2392.92,1179.83) 2392.92,1182.12 ccw(c2392.92,1184.4) 2395.2,1184.4 2395.2,1194.83 ccw(c2392.91,1194.83) 2392.92,1197.12 cw(c2392.92,1199.4) 2390.63,1199.4 2390.63,1209.83 cw(c2392.92,1209.83) 2392.92,1212.12 ccw(c2392.92,1214.4) 2395.2,1214.4 2395.2,1224.83 ccw(c2392.91,1224.83) 2392.92,1227.12 cw(c2392.92,1229.4) 2390.63,1229.4 2390.63,1239.83 cw(c2392.92,1239.83) 2392.92,1242.12 ccw(c2392.92,1244.4) 2395.2,1244.4 2395.2,1254.83 ccw(c2392.91,1254.83) 2392.92,1257.12 cw(c2392.92,1259.4) 2390.63,1259.4 2390.63,1269.83 cw(c2392.92,1269.83) 2392.92,1272.12 ccw(c2392.92,1274.4) 2395.2,1274.4 2395.2,1284.83 ccw(c2392.91,1284.83) 2392.92,1287.12 cw(c2392.92,1289.4) 2390.63,1289.4 2390.63,1299.83 cw(c2392.92,1299.83) 2392.92,1302.12 ccw(c2392.92,1304.4) 2395.2,1304.4 2395.2,1314.83 ccw(c2392.91,1314.83) 2392.92,1317.12 cw(c2392.92,1319.4) 2390.63,1319.4 2390.63,1329.83 cw(c2392.92,1329.83) 2392.92,1332.12 ccw(c2392.92,1334.4) 2395.2,1334.4 2395.2,1344.85 U2.AC21@2395.31,1344.96
SDQ11: U2.AB20 UD2.R10 | length 943.7
  Top Layer w5: UD2.R10@2303.54,790.94 2315.45,802.85 2326.39,802.85 2342.82,819.28 2342.82,828.85 2347.82,833.85 2372.39,833.85 2377.39,838.85 2377.39,904.07 2358.19,923.26 2343.19,923.26 cw(c2343.19,928.07) 2338.38,928.07 ccw(c2333.57,928.07) 2333.57,932.88 2328.19,932.88 ccw(c2328.19,928.07) 2323.38,928.07 cw(c2318.57,928.07) 2318.57,923.26 2308.19,923.26 2280,951.46 2280,966.46 cw(c2287.5,966.46) 2287.5,973.96 2297.5,973.96 ccw(c2297.5,981.46) 2297.5,988.96 2287.5,988.96 cw(c2287.5,996.46) 2287.5,1003.96 2297.5,1003.96 ccw(c2297.5,1011.46) 2297.5,1018.96 2287.5,1018.96 cw(c2287.5,1026.46) 2287.5,1033.96 2297.5,1033.96 ccw(c2297.5,1041.46) 2297.5,1048.96 2287.5,1048.96 cw(c2287.5,1056.46) 2280,1056.46 2280,1061.46 2375,1156.46 2375,1167.09 ccw(c2368.51,1167.09) 2368.51,1173.57 cw(c2368.51,1180.06) 2362.03,1180.06 2362.03,1182.09 cw(c2368.51,1182.09) 2368.51,1188.57 ccw(c2368.51,1195.06) 2375,1195.06 2375,1197.09 ccw(c2368.51,1197.09) 2368.51,1203.57 cw(c2368.51,1210.06) 2362.03,1210.06 2362.03,1212.09 cw(c2368.51,1212.09) 2368.51,1218.57 ccw(c2368.51,1225.06) 2375,1225.06 2375,1227.09 ccw(c2368.51,1227.09) 2368.51,1233.57 cw(c2368.51,1240.06) 2362.03,1240.06 2362.03,1242.09 cw(c2368.51,1242.09) 2368.51,1248.57 ccw(c2368.51,1255.06) 2375,1255.06 2375,1257.09 ccw(c2368.51,1257.09) 2368.51,1263.57 cw(c2368.51,1270.06) 2362.03,1270.06 2362.03,1272.09 cw(c2368.51,1272.09) 2368.51,1278.57 ccw(c2368.51,1285.06) 2375,1285.06 2375,1287.09 ccw(c2368.51,1287.09) 2368.51,1293.57 cw(c2368.51,1300.06) 2362.03,1300.06 2362.03,1302.09 cw(c2368.51,1302.09) 2368.51,1308.57 ccw(c2368.51,1315.06) 2375,1315.06 2375,1325.33 2381.13,1331.46 2381.13,1359.15 U2.AB20@2369.72,1370.55
SDQ12: U2.AB23 UD2.T9 | length 946.1
  Top Layer w4: UD2.T9@2329.13,756.05 2343.73,741.46 2363.12,741.46 2373.12,751.46
  Top Layer w5: UD2.T9@2329.13,756.05 UD2.T9@2329.13,759.45 ; 2373.12,751.46 2375,751.46 2382.99,759.45 2402.99,759.45 2443.45,799.91 2443.45,828.94 cw(c2449.19,828.94) 2449.19,834.68 ccw(c2449.19,840.42) 2454.93,840.42 2454.93,843.94 ccw(c2449.19,843.94) 2449.19,849.68 cw(c2449.19,855.41) 2443.45,855.41 2443.45,858.94 cw(c2449.19,858.94) 2449.19,864.68 ccw(c2449.19,870.42) 2454.93,870.42 2454.93,873.94 ccw(c2449.19,873.94) 2449.19,879.68 cw(c2449.19,885.41) 2443.45,885.41 2443.45,888.94 cw(c2449.19,888.94) 2449.19,894.68 ccw(c2449.19,900.42) 2454.93,900.42 2454.93,903.94 ccw(c2449.19,903.94) 2449.19,909.68 cw(c2449.19,915.41) 2443.45,915.41 2443.45,918.94 cw(c2449.19,918.94) 2449.19,924.68 ccw(c2449.19,930.42) 2454.93,930.42 2454.93,933.94 ccw(c2449.19,933.94) 2449.19,939.68 cw(c2449.19,945.41) 2443.45,945.41 2443.45,948.94 cw(c2449.19,948.94) 2449.19,954.68 ccw(c2449.19,960.42) 2454.93,960.42 2454.93,963.94 ccw(c2449.19,963.94) 2449.19,969.68 cw(c2449.19,975.41) 2443.45,975.41 2443.45,978.94 cw(c2449.19,978.94) 2449.19,984.68 ccw(c2449.19,990.42) 2454.93,990.42 2454.93,993.94 ccw(c2449.19,993.94) 2449.19,999.68 cw(c2449.19,1005.41) 2443.45,1005.41 2443.45,1008.94 cw(c2449.19,1008.94) 2449.19,1014.68 ccw(c2449.19,1020.42) 2454.93,1020.42 2454.93,1023.94 ccw(c2449.19,1023.94) 2449.19,1029.68 cw(c2449.19,1035.41) 2443.45,1035.41 2443.45,1038.94 cw(c2449.19,1038.94) 2449.19,1044.68 ccw(c2449.19,1050.42) 2454.93,1050.42 2454.93,1053.94 ccw(c2449.19,1053.94) 2449.19,1059.68 cw(c2449.19,1065.41) 2443.45,1065.41 2443.45,1068.94 cw(c2449.19,1068.94) 2449.19,1074.68 ccw(c2449.19,1080.42) 2454.93,1080.42 2454.93,1083.94 ccw(c2449.19,1083.94) 2449.19,1089.68 cw(c2449.19,1095.41) 2443.45,1095.41 2443.45,1098.94 cw(c2449.19,1098.94) 2449.19,1104.68 ccw(c2449.19,1110.42) 2454.93,1110.42 2454.93,1113.94 ccw(c2449.19,1113.94) 2449.19,1119.68 cw(c2449.19,1125.41) 2443.45,1125.41 2443.45,1128.94 cw(c2449.19,1128.94) 2449.19,1134.68 ccw(c2449.19,1140.42) 2454.93,1140.42 2454.93,1143.94 ccw(c2449.19,1143.94) 2449.19,1149.68 cw(c2449.19,1155.41) 2443.45,1155.41 2443.45,1158.94 cw(c2449.19,1158.94) 2449.19,1164.68 ccw(c2449.19,1170.42) 2454.93,1170.42 2454.93,1173.94 ccw(c2449.19,1173.94) 2449.19,1179.68 cw(c2449.19,1185.41) 2443.45,1185.41 2443.45,1188.94 cw(c2449.19,1188.94) 2449.19,1194.68 ccw(c2449.19,1200.42) 2454.93,1200.42 2454.93,1203.94 ccw(c2449.19,1203.94) 2449.19,1209.68 cw(c2449.19,1215.41) 2443.45,1215.41 2443.45,1218.94 cw(c2449.19,1218.94) 2449.19,1224.68 ccw(c2449.19,1230.42) 2454.93,1230.42 2454.93,1233.94 ccw(c2449.19,1233.94) 2449.19,1239.68 cw(c2449.19,1245.41) 2443.45,1245.41 2443.45,1248.94 cw(c2449.19,1248.94) 2449.19,1254.68 ccw(c2449.19,1260.42) 2454.93,1260.42 2454.93,1263.94 ccw(c2449.19,1263.94) 2449.19,1269.68 cw(c2449.19,1275.41) 2443.45,1275.41 2443.45,1278.94 cw(c2449.19,1278.94) 2449.19,1284.68 ccw(c2449.19,1290.42) 2454.93,1290.42 2454.93,1293.94 ccw(c2449.19,1293.94) 2449.19,1299.68 cw(c2449.19,1305.41) 2443.45,1305.41 2443.45,1316.52 2462,1335.07 2462,1361.45 2452.9,1370.55 U2.AB23@2446.5,1370.55
SDQ13: U2.AA23 UD2.R9 | length 951.7
  Top Layer w5: UD2.R9@2303.54,759.45 2315.45,747.54 2315.45,716.01 2323.91,707.55 2422.35,707.55 2428.98,714.18 ccw(c2423.68,719.48) 2428.98,724.78 2424.99,728.77 cw(c2430.29,734.08) 2435.6,739.38 2439.59,735.39 ccw(c2444.89,740.69) 2450.19,746 2446.2,749.99 cw(c2451.51,755.29) 2456.81,760.59 2460.8,756.6 ccw(c2466.1,761.91) 2471.41,756.6 2480,765.2 2480,1379.21 2463.07,1396.14 U2.AA23@2446.5,1396.14
SDQ14: U2.AA22 UD2.T8 | length 949.9
  Top Layer w5: UD2.T8@2329.13,727.95 2338.59,727.95 2350,716.55 2381.04,716.55 2471,806.51 2471,818.08 ccw(c2466.87,818.08) 2466.87,822.21 cw(c2466.87,826.34) 2462.74,826.34 2462.74,833.08 cw(c2466.87,833.08) 2466.87,837.21 ccw(c2466.87,841.34) 2471,841.34 2471,849.26 ccw(c2467.46,849.26) 2467.46,852.8 cw(c2467.46,856.34) 2463.93,856.34 2463.93,864.26 cw(c2467.46,864.26) 2467.46,867.8 ccw(c2467.46,871.34) 2471,871.34 2471,879.26 ccw(c2467.46,879.26) 2467.46,882.8 cw(c2467.46,886.34) 2463.93,886.34 2463.93,894.26 cw(c2467.46,894.26) 2467.46,897.8 ccw(c2467.46,901.34) 2471,901.34 2471,909.26 ccw(c2467.46,909.26) 2467.46,912.8 cw(c2467.46,916.34) 2463.93,916.34 2463.93,924.26 cw(c2467.46,924.26) 2467.46,927.8 ccw(c2467.46,931.34) 2471,931.34 2471,939.26 ccw(c2467.46,939.26) 2467.46,942.8 cw(c2467.46,946.34) 2463.93,946.34 2463.93,954.26 cw(c2467.46,954.26) 2467.46,957.8 ccw(c2467.46,961.34) 2471,961.34 2471,969.26 ccw(c2467.46,969.26) 2467.46,972.8 cw(c2467.46,976.34) 2463.93,976.34 2463.93,984.26 cw(c2467.46,984.26) 2467.46,987.8 ccw(c2467.46,991.34) 2471,991.34 2471,999.26 ccw(c2467.46,999.26) 2467.46,1002.8 cw(c2467.46,1006.34) 2463.93,1006.34 2463.93,1014.26 cw(c2467.46,1014.26) 2467.46,1017.8 ccw(c2467.46,1021.34) 2471,1021.34 2471,1029.26 ccw(c2467.46,1029.26) 2467.46,1032.8 cw(c2467.46,1036.34) 2463.93,1036.34 2463.93,1044.26 cw(c2467.46,1044.26) 2467.46,1047.8 ccw(c2467.46,1051.34) 2471,1051.34 2471,1059.26 ccw(c2467.46,1059.26) 2467.46,1062.8 cw(c2467.46,1066.34) 2463.93,1066.34 2463.93,1074.26 cw(c2467.46,1074.26) 2467.46,1077.8 ccw(c2467.46,1081.34) 2471,1081.34 2471,1089.26 ccw(c2467.46,1089.26) 2467.46,1092.8 cw(c2467.46,1096.34) 2463.93,1096.34 2463.93,1104.26 cw(c2467.46,1104.26) 2467.46,1107.8 ccw(c2467.46,1111.34) 2471,1111.34 2471,1119.26 ccw(c2467.46,1119.26) 2467.46,1122.8 cw(c2467.46,1126.34) 2463.93,1126.34 2463.93,1134.26 cw(c2467.46,1134.26) 2467.46,1137.8 ccw(c2467.46,1141.34) 2471,1141.34 2471,1149.26 ccw(c2467.46,1149.26) 2467.46,1152.8 cw(c2467.46,1156.34) 2463.93,1156.34 2463.93,1164.26 cw(c2467.46,1164.26) 2467.46,1167.8 ccw(c2467.46,1171.34) 2471,1171.34 2471,1179.26 ccw(c2467.46,1179.26) 2467.46,1182.8 cw(c2467.46,1186.34) 2463.93,1186.34 2463.93,1194.26 cw(c2467.46,1194.26) 2467.46,1197.8 ccw(c2467.46,1201.34) 2471,1201.34 2471,1209.26 ccw(c2467.46,1209.26) 2467.46,1212.8 cw(c2467.46,1216.34) 2463.93,1216.34 2463.93,1224.26 cw(c2467.46,1224.26) 2467.46,1227.8 ccw(c2467.46,1231.34) 2471,1231.34 2471,1239.26 ccw(c2467.46,1239.26) 2467.46,1242.8 cw(c2467.46,1246.34) 2463.93,1246.34 2463.93,1254.26 cw(c2467.46,1254.26) 2467.46,1257.8 ccw(c2467.46,1261.34) 2471,1261.34 2471,1269.26 ccw(c2467.46,1269.26) 2467.46,1272.8 cw(c2467.46,1276.34) 2463.93,1276.34 2463.93,1284.26 cw(c2467.46,1284.26) 2467.46,1287.8 ccw(c2467.46,1291.34) 2471,1291.34 2471,1299.26 ccw(c2467.46,1299.26) 2467.46,1302.8 cw(c2467.46,1306.34) 2463.93,1306.34 2463.93,1314.26 cw(c2467.46,1314.26) 2467.46,1317.8 ccw(c2467.46,1321.34) 2471,1321.34 2471,1374.64 2461.4,1384.24 2432.22,1384.24 2420.91,1395.55 U2.AA22@2420.91,1396.14
SDQ15: U2.Y22 UD2.R8 | length 941.1
  Top Layer w5: UD2.R8@2303.54,727.95 2303.54,707.91 2312.91,698.55 2426.08,698.55 2489,761.47 2489,1382.94 2462.11,1409.83 2432.81,1409.83 U2.Y22@2420.91,1421.73
SDQ16: U2.AC6 UD2.E9 | length 852.5
  Top Layer w5: U2.AC6@2011.46,1344.96 2011.46,1275.77 v1@2014.02,1273.21 ; v1(2035.17,711.6) 2051.75,711.6 2059.97,719.82 2059.97,750.08 UD2.E9@2049.3,760.75
  Bottom Layer w5: v1@2014.02,1273.21 2002.68,1261.87 1999.53,1261.87 1997.69,1260.03 1994.47,1260.03 1982.74,1248.3 ccw(c1981.13,1246.69) 1979.52,1248.3 1972.13,1240.91 ccw(c1973.74,1239.3) 1972.13,1237.69 cw(c1970.52,1236.08) 1972.13,1234.47 1964.74,1227.09 cw(c1963.13,1228.69) 1961.53,1227.09 ccw(c1959.92,1225.48) 1958.31,1227.09 1950.92,1219.7 ccw(c1952.53,1218.09) 1950.92,1216.48 cw(c1949.31,1214.87) 1950.92,1213.26 1940,1202.34 1940,772.43 1973.89,738.54 cw(c1973.89,733.81) 1977.23,737.15 1989.7,724.69 ccw(c1993.96,728.96) 1993.96,722.92 ccw(c1993.96,728.96) 1998.23,724.69 ccw(c1993.96,728.96) 2000,728.96 2000,736.46 cw(c2008.54,736.46) 2002.5,742.49 cw(c2008.54,736.46) 2008.54,744.99 2018.96,744.99 cw(c2018.96,738.96) 2023.23,743.22 cw(c2018.96,738.96) 2025,738.96 2025,736.16 ccw(c2059.72,736.16) v1(2035.17,711.6) ; v1@2032.83,713.06 ccw(c2038.21,713.06) v1@2038.21,707.68
  other v1: 2012.12,1274.72
SDQ17: U2.AB6 UD2.F8 | length 852.2
  Top Layer w5: v1(1997.46,1303.08) 2000.05,1305.68 2000.05,1361.51 2009.09,1370.55 U2.AB6@2011.46,1370.55
  Bottom Layer w4: 1980.75,1263.6 1981.91,1263.6 1998.18,1279.87 1998.18,1302.36 v1(1997.46,1303.08)
  Bottom Layer w5: 1980.75,1263.6 1974.45,1257.3 cw(c1972.3,1259.45) 1970.15,1257.3 ccw(c1968,1255.15) 1965.84,1257.3 1959.54,1251 ccw(c1961.69,1248.85) 1959.54,1246.69 cw(c1957.39,1244.54) 1959.54,1242.39 1953.24,1236.09 cw(c1951.09,1238.24) 1948.93,1236.09 ccw(c1946.78,1233.93) 1944.63,1236.09 1938.33,1229.78 ccw(c1940.48,1227.63) 1938.33,1225.48 cw(c1936.18,1223.33) 1938.33,1221.18 1931,1213.85 1931,895.45 cw(c1924.29,895.45) 1924.29,888.74 ccw(c1924.29,882.03) 1917.58,882.03 1917.58,880.45 ccw(c1924.29,880.45) 1924.29,873.74 cw(c1924.29,867.03) 1931,867.03 1931,768.7 2002.6,697.1 2048.7,697.1 v1(2075.43,723.83)
SDQ18: U2.AC7 UD2.F9 | length 852.6
  Top Layer w4.5: v1(2015.65,1226.1) 2037.05,1247.5
  Top Layer w5: 2037.05,1247.5 U2.AC7@2037.05,1344.96
  Bottom Layer w4: 1974.74,871.71 1980,866.46 1981.54,866.46 cw(c1981.54,862.99) 1985,862.99 ccw(c1994.18,861.42) 1984.87,861.42 1984.87,849.05 ccw(c1994.18,849.05) 1985,847.48 1985,831.46 ; 2025,776.46 ccw(c2030.24,781.7) 2030.24,774.29 2068.4,774.29 cw(c2068.4,769.46) 2071.81,772.87 cw(c2068.4,769.46) 2073.23,769.46 v1(2073.23,764.45)
  Bottom Layer w5: 1974.74,871.71 1965.95,880.51 1965.95,996.57 cw(c1971.23,996.57) 1971.23,1001.85 ccw(c1971.23,1007.12) 1976.5,1007.12 1976.5,1016.57 ccw(c1971.23,1016.57) 1971.23,1021.85 cw(c1971.23,1027.12) 1965.95,1027.12 1965.95,1042.12 cw(c1973.45,1042.12) 1973.45,1049.62 1974.77,1049.62 ccw(c1974.77,1057.12) 1974.77,1064.62 1973.45,1064.62 cw(c1973.45,1072.12) 1973.45,1079.62 1974.77,1079.62 ccw(c1974.77,1087.12) 1974.77,1094.62 1973.45,1094.62 cw(c1973.45,1102.12) 1973.45,1109.62 1974.77,1109.62 ccw(c1974.77,1117.12) 1974.77,1124.62 1973.45,1124.62 cw(c1973.45,1132.12) 1973.45,1139.62 1974.77,1139.62 ccw(c1974.77,1147.12) 1974.77,1154.62 1973.45,1154.62 cw(c1973.45,1162.12) 1965.95,1162.12 1965.95,1172.61 1974,1180.66 1974,1190.46 1986,1202.46 1990.8,1202.46 1999,1210.66 1999,1215.46 2009.65,1226.1 v1(2015.65,1226.1) ; 1985,831.46 1985,821.46 cw(c1975,821.46) 1975,811.46 ccw(c1975,806.46) 1970,806.46 1970,801.46 cw(c1970,791.46) 1980,791.46 1980,781.46 ccw(c1990,781.46) 1990,771.46 ccw(c1990,776.46) 1995,776.46 1995,791.46 cw(c2000,791.46) 2000,796.46 2001.2,796.46 cw(c2001.2,784.97) 2009.32,793.09 cw(c2007.69,791.46) 2010,791.46 ccw(c2025,791.46) 2025,776.46
SDQ19: U2.AB7 UD2.D9 | length 845.1
  Top Layer w5: v1(2005.33,1247.87) 2021.42,1247.87 2022,1248.46 ccw(c2022,1251.46) 2025,1251.46 ccw(c2020,1251.46) 2020,1256.46 2020,1262.05 ccw(c2008.37,1270.71) 2021.07,1263.71 2028.05,1263.71 2028.05,1278.6 ccw(c2026.11,1278.6) 2026.11,1280.53 cw(c2026.11,1282.46) 2024.18,1282.46 2024.18,1293.6 cw(c2026.11,1293.6) 2026.11,1295.53 ccw(c2026.11,1297.46) 2028.05,1297.46 2028.05,1308.6 ccw(c2026.11,1308.6) 2026.11,1310.53 cw(c2026.11,1312.46) 2024.18,1312.46 2024.18,1323.6 cw(c2026.11,1323.6) 2026.11,1325.53 ccw(c2026.11,1327.46) 2028.05,1327.46 2028.05,1337.83 2025.64,1340.24 2025.64,1349.68 2028.95,1352.99 2028.95,1362.45 U2.AB7@2037.05,1370.55
  Bottom Layer w5: v1(2005.33,1247.87) 2000,1242.54 2000,1236.46 cw(c1995,1236.46) 1995,1231.46 ccw(c1995,1226.46) 1990,1226.46 1990,1216.46 cw(c1985,1216.46) 1985,1211.46 cw(c1985,1216.46) 1980,1216.46 ccw(c1975.92,1216.46) 1975.92,1220.54 1973.42,1220.54 ccw(c1973.42,1214.5) 1969.15,1218.77 1966.38,1216 ccw(c1968.61,1216) 1967.03,1214.42 1970,1211.46 cw(c1970,1206.46) 1975,1206.46 cw(c1970,1206.46) 1970,1201.46 1960,1201.46 ccw(c1960,1196.46) 1955,1196.46 ccw(c1960,1196.46) 1960,1191.46 cw(c1960,1186.46) 1965,1186.46 cw(c1960,1186.46) 1960,1181.46 ccw(c1960,1178.41) 1956.95,1178.41 1956.95,1168 cw(c1954.58,1168) 1954.58,1165.62 ccw(c1954.58,1163.25) 1952.2,1163.25 1952.2,1153 ccw(c1954.58,1153) 1954.58,1150.62 cw(c1954.58,1148.25) 1956.95,1148.25 1956.95,1138 cw(c1954.58,1138) 1954.58,1135.62 ccw(c1954.58,1133.25) 1952.2,1133.25 1952.2,1123 ccw(c1954.58,1123) 1954.58,1120.62 cw(c1954.58,1118.25) 1956.95,1118.25 1956.95,1108 cw(c1954.58,1108) 1954.58,1105.62 ccw(c1954.58,1103.25) 1952.2,1103.25 1952.2,1093 ccw(c1954.58,1093) 1954.58,1090.62 cw(c1954.58,1088.25) 1956.95,1088.25 1956.95,1078 cw(c1954.58,1078) 1954.58,1075.62 ccw(c1954.58,1073.25) 1952.2,1073.25 1952.2,1063 ccw(c1954.58,1063) 1954.58,1060.62 cw(c1954.58,1058.25) 1956.95,1058.25 1956.95,1048 cw(c1954.58,1048) 1954.58,1045.62 ccw(c1954.58,1043.25) 1952.2,1043.25 1952.2,1033 ccw(c1954.58,1033) 1954.58,1030.62 cw(c1954.58,1028.25) 1956.95,1028.25 1956.95,1018 cw(c1954.58,1018) 1954.58,1015.62 ccw(c1954.58,1013.25) 1952.2,1013.25 1952.2,1003 ccw(c1954.58,1003) 1954.58,1000.62 cw(c1954.58,998.25) 1956.95,998.25 1956.95,988 cw(c1954.58,988) 1954.58,985.62 ccw(c1954.58,983.25) 1952.2,983.25 1952.2,973 ccw(c1954.58,973) 1954.58,970.62 cw(c1954.58,968.25) 1956.95,968.25 1956.95,958 cw(c1954.58,958) 1954.58,955.62 ccw(c1954.58,953.25) 1952.2,953.25 1952.2,943 ccw(c1954.58,943) 1954.58,940.62 cw(c1954.58,938.25) 1956.95,938.25 1956.95,928 cw(c1954.58,928) 1954.58,925.62 ccw(c1954.58,923.25) 1952.2,923.25 1952.2,913 ccw(c1954.58,913) 1954.58,910.62 cw(c1954.58,908.25) 1956.95,908.25 1956.95,898 cw(c1954.58,898) 1954.58,895.62 ccw(c1954.58,893.25) 1952.2,893.25 1952.2,883 ccw(c1954.58,883) 1954.58,880.62 cw(c1954.58,878.25) 1956.95,878.25 1956.95,868 cw(c1954.58,868) 1954.58,865.62 ccw(c1954.58,863.25) 1952.2,863.25 1952.2,853 ccw(c1954.58,853) 1954.58,850.62 cw(c1954.58,848.25) 1956.95,848.25 1956.95,838 cw(c1954.58,838) 1954.58,835.62 ccw(c1954.58,833.25) 1952.2,833.25 1952.2,823 ccw(c1954.58,823) 1954.58,820.62 cw(c1954.58,818.25) 1956.95,818.25 1956.95,808 cw(c1954.58,808) 1954.58,805.62 ccw(c1954.58,803.25) 1952.2,803.25 1952.2,793 ccw(c1954.58,793) 1954.58,790.62 cw(c1954.58,788.25) 1956.95,788.25 1956.95,777.81 1974.31,760.46 2016.4,760.46 v1(2017.41,759.45)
